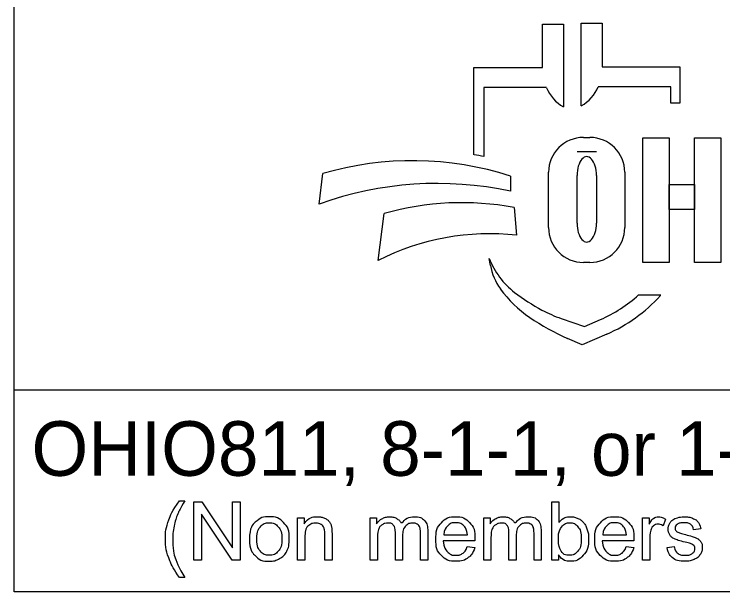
# Model space of a CAD drawing. Extents: x 0 to 34, y 0 to 22.
# Drawn here: x 2.378 to 4.196, y 2.143 to 3.625 of the extents above; entities that cross this region are included whole.
import ezdxf

# ---------------------------------------------------------------- set-up
doc = ezdxf.new("R2010")
doc.units = 0
doc.layers.add('SH_Data', color=7, linetype='Continuous')
doc.layers.add('SH_Text', color=7, linetype='Continuous')

msp = doc.modelspace()

# ---------------------------------------------------------------- linework, layer by layer
at = {"layer": 'SH_Data'}
for p, q in [((2.3775, 2.1428), (2.3775, 4.4803)), ((2.3775, 2.1428), (2.3775, 4.4803)), ((6.6275, 2.6607), (2.3775, 2.6607)), ((6.6275, 2.6607), (2.3775, 2.6607)), ((6.6275, 2.1428), (2.3775, 2.1428)), ((6.6275, 2.1428), (2.3775, 2.1428))]:
    msp.add_line(p, q, dxfattribs=at)
at = {"layer": 'SH_Text'}
for p, q in [((3.8329, 3.39), (3.8329, 3.6021)), ((3.8329, 3.6021), (3.8865, 3.6021)), ((3.8329, 3.39), (3.8329, 3.6021)), ((3.8329, 3.6021), (3.8865, 3.6021)), ((3.8865, 3.6021), (3.8865, 3.4906)), ((3.8865, 3.6021), (3.8865, 3.4906)), ((3.7335, 3.4883), (3.7335, 3.5998)), ((3.7335, 3.5998), (3.7872, 3.5998)), ((3.7335, 3.4883), (3.7335, 3.5998)), ((3.7335, 3.5998), (3.7872, 3.5998)), ((3.7872, 3.5998), (3.7872, 3.3877)), ((3.7872, 3.5998), (3.7872, 3.3877)), ((3.5576, 3.2644), (3.5576, 3.4883)), ((3.5576, 3.4883), (3.7335, 3.4883)), ((3.5576, 3.2644), (3.5576, 3.4883)), ((3.5576, 3.4883), (3.7335, 3.4883)), ((3.8865, 3.4906), (4.0857, 3.4906)), ((3.8865, 3.4906), (4.0857, 3.4906)), ((4.0857, 3.4906), (4.0857, 3.3968)), ((4.0857, 3.4906), (4.0857, 3.3968)), ((4.0625, 3.4392), (3.8761, 3.4392)), ((4.0625, 3.4392), (3.8761, 3.4392)), ((4.0625, 3.3968), (4.0625, 3.4392)), ((4.0625, 3.3968), (4.0625, 3.4392)), ((3.5828, 3.4369), (3.5828, 3.26)), ((3.7439, 3.4369), (3.5828, 3.4369)), ((3.5828, 3.4369), (3.5828, 3.26)), ((3.7439, 3.4369), (3.5828, 3.4369)), ((4.0857, 3.3968), (4.0625, 3.3968)), ((4.0857, 3.3968), (4.0625, 3.3968)), ((3.8385, 3.3091), (3.8551, 3.3091)), ((3.8385, 3.3091), (3.8551, 3.3091)), ((3.8718, 3.2721), (3.822, 3.2721)), ((3.8718, 3.2721), (3.822, 3.2721)), ((3.7491, 3.0776), (3.7491, 3.2196)), ((3.7491, 3.0776), (3.7491, 3.2196)), ((3.9445, 3.2196), (3.9445, 3.0776)), ((3.9445, 3.2196), (3.9445, 3.0776)), ((3.1602, 3.1381), (3.1696, 3.2162)), ((3.1602, 3.1381), (3.1696, 3.2162)), ((3.6509, 3.2097), (3.6509, 3.1709)), ((3.6509, 3.2097), (3.6509, 3.1709)), ((3.822, 3.089), (3.822, 3.2114)), ((3.822, 3.089), (3.822, 3.2114)), ((3.8718, 3.2114), (3.8718, 3.089)), ((3.8718, 3.2114), (3.8718, 3.089)), ((3.6608, 3.1291), (3.6671, 3.0582)), ((3.6608, 3.1291), (3.6671, 3.0582)), ((3.312, 2.9936), (3.3267, 3.1137)), ((3.312, 2.9936), (3.3267, 3.1137)), ((3.5997, 2.9807), (3.5967, 2.9986)), ((3.5997, 2.9807), (3.5967, 2.9986)), ((3.8551, 2.9882), (3.8385, 2.9882)), ((3.8551, 2.9882), (3.8385, 2.9882)), ((3.98, 2.9048), (4.0375, 2.9048)), ((3.98, 2.9048), (4.0375, 2.9048)), ((3.7816, 2.8444), (3.841, 2.8239)), ((3.7816, 2.8444), (3.841, 2.8239)), ((3.841, 2.8239), (3.8821, 2.8417)), ((3.841, 2.8239), (3.8821, 2.8417)), ((3.8983, 2.8044), (3.835, 2.7769)), ((3.8983, 2.8044), (3.835, 2.7769)), ((3.835, 2.7769), (3.7976, 2.7934)), ((3.835, 2.7769), (3.7976, 2.7934))]:
    msp.add_line(p, q, dxfattribs=at)
for points in [[(3.991, 3.3081), (4.0589, 3.3081), (4.0589, 2.9881), (3.991, 2.9881)], [(3.991, 3.3081), (4.0589, 3.3081), (4.0589, 2.9881), (3.991, 2.9881)], [(4.1231, 3.3081), (4.1911, 3.3081), (4.1911, 2.9881), (4.1231, 2.9881)], [(4.1231, 3.3081), (4.1911, 3.3081), (4.1911, 2.9881), (4.1231, 2.9881)], [(4.0589, 3.1882), (4.1231, 3.1882), (4.1231, 3.1242), (4.0589, 3.1242)], [(4.0589, 3.1882), (4.1231, 3.1882), (4.1231, 3.1242), (4.0589, 3.1242)]]:
    msp.add_lwpolyline(points, close=True, dxfattribs=at)
for points in [[(2.8021, 2.3766), (2.8153, 2.3766)], [(2.8021, 2.3766), (2.8153, 2.3766)], [(2.8389, 2.2239), (2.8389, 2.3741), (2.8592, 2.3741), (2.9382, 2.2561), (2.9382, 2.3741), (2.9572, 2.3741), (2.9572, 2.2239), (2.9369, 2.2239), (2.8579, 2.3419), (2.8579, 2.2239), (2.8389, 2.2239)], [(2.8389, 2.2239), (2.8389, 2.3741), (2.8592, 2.3741), (2.9382, 2.2561), (2.9382, 2.3741), (2.9572, 2.3741), (2.9572, 2.2239), (2.9369, 2.2239), (2.8579, 2.3419), (2.8579, 2.2239), (2.8389, 2.2239)], [(3.7743, 2.2239), (3.7573, 2.2239), (3.7573, 2.3741), (3.7757, 2.3741), (3.7757, 2.3206)], [(3.7743, 2.2239), (3.7573, 2.2239), (3.7573, 2.3741), (3.7757, 2.3741), (3.7757, 2.3206)], [(3.1048, 2.2239), (3.1048, 2.3328), (3.1214, 2.3328), (3.1214, 2.3173)], [(3.1048, 2.2239), (3.1048, 2.3328), (3.1214, 2.3328), (3.1214, 2.3173)], [(3.2912, 2.2239), (3.2912, 2.3328), (3.3077, 2.3328), (3.3077, 2.3174)], [(3.2912, 2.2239), (3.2912, 2.3328), (3.3077, 2.3328), (3.3077, 2.3174)], [(3.5826, 2.2239), (3.5826, 2.3328), (3.5991, 2.3328), (3.5991, 2.3174)], [(3.5826, 2.2239), (3.5826, 2.3328), (3.5991, 2.3328), (3.5991, 2.3174)], [(3.9904, 2.2239), (3.9904, 2.3328), (4.007, 2.3328), (4.007, 2.3163)], [(3.9904, 2.2239), (3.9904, 2.3328), (4.007, 2.3328), (4.007, 2.3163)], [(4.0495, 2.3293), (4.043, 2.3122)], [(4.0495, 2.3293), (4.043, 2.3122)], [(3.3743, 2.2871), (3.3743, 2.2239), (3.3559, 2.2239), (3.3559, 2.2946)], [(3.3743, 2.2871), (3.3743, 2.2239), (3.3559, 2.2239), (3.3559, 2.2946)], [(3.4388, 2.2986), (3.4388, 2.2239), (3.4203, 2.2239), (3.4203, 2.2924)], [(3.4388, 2.2986), (3.4388, 2.2239), (3.4203, 2.2239), (3.4203, 2.2924)], [(3.6657, 2.2871), (3.6657, 2.2239), (3.6473, 2.2239), (3.6473, 2.2946)], [(3.6657, 2.2871), (3.6657, 2.2239), (3.6473, 2.2239), (3.6473, 2.2946)], [(3.7301, 2.2986), (3.7301, 2.2239), (3.7117, 2.2239), (3.7117, 2.2924)], [(3.7301, 2.2986), (3.7301, 2.2239), (3.7117, 2.2239), (3.7117, 2.2924)], [(4.1394, 2.3046), (4.1213, 2.3022)], [(4.1394, 2.3046), (4.1213, 2.3022)], [(3.1233, 2.2833), (3.1233, 2.2239), (3.1048, 2.2239)], [(3.1233, 2.2833), (3.1233, 2.2239), (3.1048, 2.2239)], [(3.1932, 2.2908), (3.1932, 2.2239), (3.1748, 2.2239), (3.1748, 2.2901)], [(3.1932, 2.2908), (3.1932, 2.2239), (3.1748, 2.2239), (3.1748, 2.2901)], [(3.3097, 2.2803), (3.3097, 2.2239), (3.2912, 2.2239)], [(3.3097, 2.2803), (3.3097, 2.2239), (3.2912, 2.2239)], [(3.56, 2.2736), (3.4788, 2.2736)], [(3.56, 2.2736), (3.4788, 2.2736)], [(3.4799, 2.2887), (3.5406, 2.2887)], [(3.4799, 2.2887), (3.5406, 2.2887)], [(3.601, 2.2803), (3.601, 2.2239), (3.5826, 2.2239)], [(3.601, 2.2803), (3.601, 2.2239), (3.5826, 2.2239)], [(3.968, 2.2736), (3.8868, 2.2736)], [(3.968, 2.2736), (3.8868, 2.2736)], [(3.8879, 2.2887), (3.9486, 2.2887)], [(3.8879, 2.2887), (3.9486, 2.2887)], [(4.0088, 2.2809), (4.0088, 2.2239), (3.9904, 2.2239)], [(4.0088, 2.2809), (4.0088, 2.2239), (3.9904, 2.2239)], [(3.5404, 2.2591), (3.5595, 2.2567)], [(3.5404, 2.2591), (3.5595, 2.2567)], [(3.9484, 2.2591), (3.9675, 2.2567)], [(3.9484, 2.2591), (3.9675, 2.2567)], [(4.053, 2.2564), (4.0712, 2.2593)], [(4.053, 2.2564), (4.0712, 2.2593)], [(3.7743, 2.2375), (3.7743, 2.2239)], [(3.7743, 2.2375), (3.7743, 2.2239)], [(2.8153, 2.1798), (2.8021, 2.1798)], [(2.8153, 2.1798), (2.8021, 2.1798)]]:
    msp.add_lwpolyline(points, dxfattribs=at)
for centre, radius, start, end in [((3.7847, 3.476), 0.0985, 299.2531, 338.0704), ((3.7847, 3.476), 0.0985, 299.2531, 338.0704), ((3.8353, 3.4736), 0.0985, 201.9296, 240.7469), ((3.8353, 3.4736), 0.0985, 201.9296, 240.7469), ((3.8385, 3.2196), 0.0895, 90, 180), ((3.8385, 3.2196), 0.0895, 90, 180), ((3.8551, 3.2196), 0.0895, 0, 90), ((3.8551, 3.2196), 0.0895, 0, 90), ((3.4295, 2.4554), 0.8191, 79.2074, 81.0007), ((3.4295, 2.4554), 0.8191, 79.2074, 81.0007), ((3.3997, 2.4302), 0.8191, 72.1402, 106.3144), ((3.3997, 2.4302), 0.8191, 72.1402, 106.3144), ((3.4628, 2.2991), 0.8919, 77.8238, 109.8274), ((3.4628, 2.2991), 0.8919, 77.8238, 109.8274), ((3.5267, 2.4094), 0.7322, 79.44, 105.8467), ((3.5267, 2.4094), 0.7322, 79.44, 105.8467), ((3.8385, 3.0776), 0.0895, 180, 270), ((3.8385, 3.0776), 0.0895, 180, 270), ((3.8551, 3.0776), 0.0895, 270, 0), ((3.8551, 3.0776), 0.0895, 270, 0), ((3.5987, 2.4262), 0.6357, 83.8248, 116.8021), ((3.5987, 2.4262), 0.6357, 83.8248, 116.8021), ((3.7841, 3.0707), 0.2008, 201.0457, 232.5314), ((3.7841, 3.0707), 0.2008, 201.0457, 232.5314), ((3.741, 3.0048), 0.1433, 189.6817, 216.0884), ((3.741, 3.0048), 0.1433, 189.6817, 216.0884), ((3.8747, 3.1022), 0.3088, 216.0884, 235.7167), ((3.8747, 3.1022), 0.3088, 216.0884, 235.7167), ((3.9766, 3.3219), 0.5173, 232.5314, 241.794), ((3.9766, 3.3219), 0.5173, 232.5314, 241.794), ((3.7387, 3.1722), 0.3602, 293.4582, 312.0712), ((3.7387, 3.1722), 0.3602, 293.4582, 312.0712), ((3.7387, 3.1722), 0.401, 293.4582, 317.8286), ((3.7387, 3.1722), 0.401, 293.4582, 317.8286), ((3.8914, 3.1631), 0.3371, 241.794, 250.9821), ((3.8914, 3.1631), 0.3371, 241.794, 250.9821), ((4.0412, 3.3465), 0.6044, 235.7167, 246.2325), ((4.0412, 3.3465), 0.6044, 235.7167, 246.2325)]:
    msp.add_arc(centre, radius, start, end, dxfattribs=at)
for centre, start_param, end_param in [((3.8469, 3.2114), 4.712389, 7.853982), ((3.8469, 3.2114), 4.712389, 7.853982), ((3.8469, 3.089), 1.570796, 4.712389), ((3.8469, 3.089), 1.570796, 4.712389)]:
    msp.add_ellipse(centre, major_axis=(0, 0.0484), ratio=0.514403, start_param=start_param, end_param=end_param, dxfattribs=at)
for points in [[(2.8021, 2.1798), (2.7869, 2.199), (2.7763, 2.2248), (2.7657, 2.2506), (2.7657, 2.2783), (2.7657, 2.3026), (2.7736, 2.325), (2.7829, 2.3509), (2.8021, 2.3766)], [(2.8021, 2.1798), (2.7869, 2.199), (2.7763, 2.2248), (2.7657, 2.2506), (2.7657, 2.2783), (2.7657, 2.3026), (2.7736, 2.325), (2.7829, 2.3509), (2.8021, 2.3766)], [(2.8153, 2.3766), (2.8029, 2.3553), (2.7989, 2.3462), (2.7927, 2.332), (2.7891, 2.3167), (2.7847, 2.2975), (2.7847, 2.2782), (2.7847, 2.2289), (2.8153, 2.1798)], [(2.8153, 2.3766), (2.8029, 2.3553), (2.7989, 2.3462), (2.7927, 2.332), (2.7891, 2.3167), (2.7847, 2.2975), (2.7847, 2.2782), (2.7847, 2.2289), (2.8153, 2.1798)], [(2.9814, 2.2783), (2.9814, 2.3085), (2.9981, 2.3231), (3.0122, 2.3352), (3.0323, 2.3352), (3.0547, 2.3352), (3.069, 2.3205), (3.0832, 2.3058), (3.0832, 2.2799), (3.0832, 2.2589), (3.0769, 2.2469), (3.0706, 2.2348), (3.0586, 2.2282), (3.0466, 2.2215), (3.0323, 2.2215), (3.0095, 2.2215), (2.9954, 2.2362), (2.9814, 2.2508), (2.9814, 2.2783)], [(2.9814, 2.2783), (2.9814, 2.3085), (2.9981, 2.3231), (3.0122, 2.3352), (3.0323, 2.3352), (3.0547, 2.3352), (3.069, 2.3205), (3.0832, 2.3058), (3.0832, 2.2799), (3.0832, 2.2589), (3.0769, 2.2469), (3.0706, 2.2348), (3.0586, 2.2282), (3.0466, 2.2215), (3.0323, 2.2215), (3.0095, 2.2215), (2.9954, 2.2362), (2.9814, 2.2508), (2.9814, 2.2783)], [(3.1214, 2.3173), (3.1334, 2.3352), (3.156, 2.3352), (3.1659, 2.3352), (3.1741, 2.3316), (3.1823, 2.3281), (3.1864, 2.3224), (3.1905, 2.3166), (3.1922, 2.3087), (3.1932, 2.3036), (3.1932, 2.2908)], [(3.1214, 2.3173), (3.1334, 2.3352), (3.156, 2.3352), (3.1659, 2.3352), (3.1741, 2.3316), (3.1823, 2.3281), (3.1864, 2.3224), (3.1905, 2.3166), (3.1922, 2.3087), (3.1932, 2.3036), (3.1932, 2.2908)], [(3.3077, 2.3174), (3.3128, 2.3254), (3.3214, 2.3303), (3.3299, 2.3352), (3.3407, 2.3352), (3.3528, 2.3352), (3.3606, 2.3301), (3.3683, 2.3251), (3.3715, 2.3161), (3.3844, 2.3352), (3.4051, 2.3352), (3.4213, 2.3352), (3.43, 2.3262), (3.4388, 2.3172), (3.4388, 2.2986)], [(3.3077, 2.3174), (3.3128, 2.3254), (3.3214, 2.3303), (3.3299, 2.3352), (3.3407, 2.3352), (3.3528, 2.3352), (3.3606, 2.3301), (3.3683, 2.3251), (3.3715, 2.3161), (3.3844, 2.3352), (3.4051, 2.3352), (3.4213, 2.3352), (3.43, 2.3262), (3.4388, 2.3172), (3.4388, 2.2986)], [(3.5595, 2.2567), (3.555, 2.24), (3.5428, 2.2307), (3.5306, 2.2215), (3.5117, 2.2215), (3.4878, 2.2215), (3.4738, 2.2362), (3.4598, 2.2509), (3.4598, 2.2774), (3.4598, 2.3049), (3.474, 2.32), (3.4881, 2.3352), (3.5106, 2.3352), (3.5324, 2.3352), (3.5463, 2.3203), (3.5601, 2.3055), (3.5601, 2.2785), (3.5601, 2.2769), (3.56, 2.2736)], [(3.5595, 2.2567), (3.555, 2.24), (3.5428, 2.2307), (3.5306, 2.2215), (3.5117, 2.2215), (3.4878, 2.2215), (3.4738, 2.2362), (3.4598, 2.2509), (3.4598, 2.2774), (3.4598, 2.3049), (3.474, 2.32), (3.4881, 2.3352), (3.5106, 2.3352), (3.5324, 2.3352), (3.5463, 2.3203), (3.5601, 2.3055), (3.5601, 2.2785), (3.5601, 2.2769), (3.56, 2.2736)], [(3.5991, 2.3174), (3.6042, 2.3254), (3.6127, 2.3303), (3.6212, 2.3352), (3.6321, 2.3352), (3.6442, 2.3352), (3.6519, 2.3301), (3.6597, 2.3251), (3.6628, 2.3161), (3.6758, 2.3352), (3.6965, 2.3352), (3.7127, 2.3352), (3.7214, 2.3262), (3.7301, 2.3172), (3.7301, 2.2986)], [(3.5991, 2.3174), (3.6042, 2.3254), (3.6127, 2.3303), (3.6212, 2.3352), (3.6321, 2.3352), (3.6442, 2.3352), (3.6519, 2.3301), (3.6597, 2.3251), (3.6628, 2.3161), (3.6758, 2.3352), (3.6965, 2.3352), (3.7127, 2.3352), (3.7214, 2.3262), (3.7301, 2.3172), (3.7301, 2.2986)], [(3.7757, 2.3206), (3.7874, 2.3352), (3.8055, 2.3352), (3.8155, 2.3352), (3.8245, 2.3311), (3.8335, 2.3271), (3.8392, 2.3198), (3.845, 2.3124), (3.8483, 2.3021), (3.8516, 2.2918), (3.8516, 2.28), (3.8516, 2.252), (3.8378, 2.2368), (3.8239, 2.2215), (3.8046, 2.2215), (3.7853, 2.2215), (3.7743, 2.2375)], [(3.7757, 2.3206), (3.7874, 2.3352), (3.8055, 2.3352), (3.8155, 2.3352), (3.8245, 2.3311), (3.8335, 2.3271), (3.8392, 2.3198), (3.845, 2.3124), (3.8483, 2.3021), (3.8516, 2.2918), (3.8516, 2.28), (3.8516, 2.252), (3.8378, 2.2368), (3.8239, 2.2215), (3.8046, 2.2215), (3.7853, 2.2215), (3.7743, 2.2375)], [(3.9675, 2.2567), (3.963, 2.24), (3.9508, 2.2307), (3.9386, 2.2215), (3.9196, 2.2215), (3.8958, 2.2215), (3.8818, 2.2362), (3.8678, 2.2509), (3.8678, 2.2774), (3.8678, 2.3049), (3.882, 2.32), (3.8961, 2.3352), (3.9186, 2.3352), (3.9404, 2.3352), (3.9543, 2.3203), (3.9681, 2.3055), (3.9681, 2.2785), (3.9681, 2.2769), (3.968, 2.2736)], [(3.9675, 2.2567), (3.963, 2.24), (3.9508, 2.2307), (3.9386, 2.2215), (3.9196, 2.2215), (3.8958, 2.2215), (3.8818, 2.2362), (3.8678, 2.2509), (3.8678, 2.2774), (3.8678, 2.3049), (3.882, 2.32), (3.8961, 2.3352), (3.9186, 2.3352), (3.9404, 2.3352), (3.9543, 2.3203), (3.9681, 2.3055), (3.9681, 2.2785), (3.9681, 2.2769), (3.968, 2.2736)], [(4.007, 2.3163), (4.0133, 2.3278), (4.0187, 2.3315), (4.0241, 2.3352), (4.0305, 2.3352), (4.0398, 2.3352), (4.0495, 2.3293)], [(4.007, 2.3163), (4.0133, 2.3278), (4.0187, 2.3315), (4.0241, 2.3352), (4.0305, 2.3352), (4.0398, 2.3352), (4.0495, 2.3293)], [(4.0712, 2.2593), (4.0727, 2.2483), (4.0798, 2.2425), (4.0868, 2.2366), (4.0995, 2.2366), (4.1122, 2.2366), (4.1184, 2.2418), (4.1245, 2.247), (4.1245, 2.254), (4.1245, 2.2602), (4.1191, 2.2638), (4.1153, 2.2663), (4.1002, 2.2701), (4.0799, 2.2752), (4.072, 2.2789), (4.0642, 2.2827), (4.0601, 2.2893), (4.0561, 2.2959), (4.0561, 2.3038), (4.0561, 2.3111), (4.0594, 2.3173), (4.0628, 2.3235), (4.0685, 2.3276), (4.0728, 2.3308), (4.0803, 2.333), (4.0877, 2.3352), (4.0962, 2.3352), (4.109, 2.3352), (4.1187, 2.3315), (4.1284, 2.3278), (4.133, 2.3215), (4.1377, 2.3152), (4.1394, 2.3046)], [(4.0712, 2.2593), (4.0727, 2.2483), (4.0798, 2.2425), (4.0868, 2.2366), (4.0995, 2.2366), (4.1122, 2.2366), (4.1184, 2.2418), (4.1245, 2.247), (4.1245, 2.254), (4.1245, 2.2602), (4.1191, 2.2638), (4.1153, 2.2663), (4.1002, 2.2701), (4.0799, 2.2752), (4.072, 2.2789), (4.0642, 2.2827), (4.0601, 2.2893), (4.0561, 2.2959), (4.0561, 2.3038), (4.0561, 2.3111), (4.0594, 2.3173), (4.0628, 2.3235), (4.0685, 2.3276), (4.0728, 2.3308), (4.0803, 2.333), (4.0877, 2.3352), (4.0962, 2.3352), (4.109, 2.3352), (4.1187, 2.3315), (4.1284, 2.3278), (4.133, 2.3215), (4.1377, 2.3152), (4.1394, 2.3046)], [(3.0003, 2.2783), (3.0003, 2.2574), (3.0094, 2.247), (3.0185, 2.2366), (3.0323, 2.2366), (3.046, 2.2366), (3.0551, 2.2471), (3.0642, 2.2575), (3.0642, 2.279), (3.0642, 2.2991), (3.0551, 2.3095), (3.0459, 2.3199), (3.0323, 2.3199), (3.0185, 2.3199), (3.0094, 2.3096), (3.0003, 2.2992), (3.0003, 2.2783)], [(3.0003, 2.2783), (3.0003, 2.2574), (3.0094, 2.247), (3.0185, 2.2366), (3.0323, 2.2366), (3.046, 2.2366), (3.0551, 2.2471), (3.0642, 2.2575), (3.0642, 2.279), (3.0642, 2.2991), (3.0551, 2.3095), (3.0459, 2.3199), (3.0323, 2.3199), (3.0185, 2.3199), (3.0094, 2.3096), (3.0003, 2.2992), (3.0003, 2.2783)], [(3.1748, 2.2901), (3.1748, 2.3013), (3.1726, 2.3069), (3.1705, 2.3125), (3.165, 2.3158), (3.1595, 2.3191), (3.1521, 2.3191), (3.1404, 2.3191), (3.1318, 2.3117), (3.1233, 2.3042), (3.1233, 2.2833)], [(3.1748, 2.2901), (3.1748, 2.3013), (3.1726, 2.3069), (3.1705, 2.3125), (3.165, 2.3158), (3.1595, 2.3191), (3.1521, 2.3191), (3.1404, 2.3191), (3.1318, 2.3117), (3.1233, 2.3042), (3.1233, 2.2833)], [(3.3559, 2.2946), (3.3559, 2.3069), (3.3514, 2.313), (3.3469, 2.3191), (3.3366, 2.3191), (3.3288, 2.3191), (3.3222, 2.315), (3.3156, 2.311), (3.3126, 2.3031), (3.3097, 2.2952), (3.3097, 2.2803)], [(3.3559, 2.2946), (3.3559, 2.3069), (3.3514, 2.313), (3.3469, 2.3191), (3.3366, 2.3191), (3.3288, 2.3191), (3.3222, 2.315), (3.3156, 2.311), (3.3126, 2.3031), (3.3097, 2.2952), (3.3097, 2.2803)], [(3.4203, 2.2924), (3.4203, 2.3035), (3.4185, 2.3083), (3.4168, 2.3132), (3.412, 2.3162), (3.4073, 2.3191), (3.401, 2.3191), (3.3895, 2.3191), (3.3819, 2.3115), (3.3743, 2.3039), (3.3743, 2.2871)], [(3.4203, 2.2924), (3.4203, 2.3035), (3.4185, 2.3083), (3.4168, 2.3132), (3.412, 2.3162), (3.4073, 2.3191), (3.401, 2.3191), (3.3895, 2.3191), (3.3819, 2.3115), (3.3743, 2.3039), (3.3743, 2.2871)], [(3.5406, 2.2887), (3.5394, 2.3025), (3.5337, 2.3094), (3.5249, 2.3201), (3.5108, 2.3201), (3.4981, 2.3201), (3.4894, 2.3115), (3.4808, 2.303), (3.4799, 2.2887)], [(3.5406, 2.2887), (3.5394, 2.3025), (3.5337, 2.3094), (3.5249, 2.3201), (3.5108, 2.3201), (3.4981, 2.3201), (3.4894, 2.3115), (3.4808, 2.303), (3.4799, 2.2887)], [(3.6473, 2.2946), (3.6473, 2.3069), (3.6428, 2.313), (3.6383, 2.3191), (3.628, 2.3191), (3.6202, 2.3191), (3.6136, 2.315), (3.607, 2.311), (3.604, 2.3031), (3.601, 2.2952), (3.601, 2.2803)], [(3.6473, 2.2946), (3.6473, 2.3069), (3.6428, 2.313), (3.6383, 2.3191), (3.628, 2.3191), (3.6202, 2.3191), (3.6136, 2.315), (3.607, 2.311), (3.604, 2.3031), (3.601, 2.2952), (3.601, 2.2803)], [(3.7117, 2.2924), (3.7117, 2.3035), (3.7099, 2.3083), (3.7081, 2.3132), (3.7034, 2.3162), (3.6987, 2.3191), (3.6923, 2.3191), (3.6809, 2.3191), (3.6733, 2.3115), (3.6657, 2.3039), (3.6657, 2.2871)], [(3.7117, 2.2924), (3.7117, 2.3035), (3.7099, 2.3083), (3.7081, 2.3132), (3.7034, 2.3162), (3.6987, 2.3191), (3.6923, 2.3191), (3.6809, 2.3191), (3.6733, 2.3115), (3.6657, 2.3039), (3.6657, 2.2871)], [(3.7741, 2.2792), (3.7741, 2.2596), (3.7794, 2.2509), (3.7881, 2.2366), (3.8029, 2.2366), (3.815, 2.2366), (3.8238, 2.2471), (3.8326, 2.2576), (3.8326, 2.2784), (3.8326, 2.2998), (3.8241, 2.3099), (3.8157, 2.3201), (3.8038, 2.3201), (3.7917, 2.3201), (3.7829, 2.3096), (3.7741, 2.299), (3.7741, 2.2792)], [(3.7741, 2.2792), (3.7741, 2.2596), (3.7794, 2.2509), (3.7881, 2.2366), (3.8029, 2.2366), (3.815, 2.2366), (3.8238, 2.2471), (3.8326, 2.2576), (3.8326, 2.2784), (3.8326, 2.2998), (3.8241, 2.3099), (3.8157, 2.3201), (3.8038, 2.3201), (3.7917, 2.3201), (3.7829, 2.3096), (3.7741, 2.299), (3.7741, 2.2792)], [(3.9486, 2.2887), (3.9474, 2.3025), (3.9417, 2.3094), (3.9328, 2.3201), (3.9188, 2.3201), (3.9061, 2.3201), (3.8974, 2.3115), (3.8888, 2.303), (3.8879, 2.2887)], [(3.9486, 2.2887), (3.9474, 2.3025), (3.9417, 2.3094), (3.9328, 2.3201), (3.9188, 2.3201), (3.9061, 2.3201), (3.8974, 2.3115), (3.8888, 2.303), (3.8879, 2.2887)], [(4.043, 2.3122), (4.0363, 2.3162), (4.0295, 2.3162), (4.0235, 2.3162), (4.0187, 2.3125), (4.0139, 2.3089), (4.0119, 2.3024), (4.0088, 2.2926), (4.0088, 2.2809)], [(4.043, 2.3122), (4.0363, 2.3162), (4.0295, 2.3162), (4.0235, 2.3162), (4.0187, 2.3125), (4.0139, 2.3089), (4.0119, 2.3024), (4.0088, 2.2926), (4.0088, 2.2809)], [(4.1213, 2.3022), (4.1201, 2.3106), (4.1142, 2.3153), (4.1083, 2.3201), (4.0975, 2.3201), (4.0848, 2.3201), (4.0794, 2.3159), (4.0739, 2.3116), (4.0739, 2.306), (4.0739, 2.3024), (4.0762, 2.2995), (4.0785, 2.2966), (4.0833, 2.2946), (4.086, 2.2936), (4.0996, 2.2899), (4.1192, 2.2847), (4.1269, 2.2813), (4.1347, 2.278), (4.1391, 2.2717), (4.1435, 2.2653), (4.1435, 2.2559), (4.1435, 2.2467), (4.1381, 2.2386), (4.1327, 2.2304), (4.1226, 2.226), (4.1124, 2.2215), (4.0996, 2.2215), (4.0784, 2.2215), (4.0672, 2.2303), (4.0561, 2.2391), (4.053, 2.2564)], [(4.1213, 2.3022), (4.1201, 2.3106), (4.1142, 2.3153), (4.1083, 2.3201), (4.0975, 2.3201), (4.0848, 2.3201), (4.0794, 2.3159), (4.0739, 2.3116), (4.0739, 2.306), (4.0739, 2.3024), (4.0762, 2.2995), (4.0785, 2.2966), (4.0833, 2.2946), (4.086, 2.2936), (4.0996, 2.2899), (4.1192, 2.2847), (4.1269, 2.2813), (4.1347, 2.278), (4.1391, 2.2717), (4.1435, 2.2653), (4.1435, 2.2559), (4.1435, 2.2467), (4.1381, 2.2386), (4.1327, 2.2304), (4.1226, 2.226), (4.1124, 2.2215), (4.0996, 2.2215), (4.0784, 2.2215), (4.0672, 2.2303), (4.0561, 2.2391), (4.053, 2.2564)], [(3.4788, 2.2736), (3.4799, 2.2557), (3.489, 2.2462), (3.4981, 2.2366), (3.5117, 2.2366), (3.5219, 2.2366), (3.5291, 2.242), (3.5362, 2.2473), (3.5404, 2.2591)], [(3.4788, 2.2736), (3.4799, 2.2557), (3.489, 2.2462), (3.4981, 2.2366), (3.5117, 2.2366), (3.5219, 2.2366), (3.5291, 2.242), (3.5362, 2.2473), (3.5404, 2.2591)], [(3.8868, 2.2736), (3.8879, 2.2557), (3.897, 2.2462), (3.9061, 2.2366), (3.9197, 2.2366), (3.9299, 2.2366), (3.937, 2.242), (3.9442, 2.2473), (3.9484, 2.2591)], [(3.8868, 2.2736), (3.8879, 2.2557), (3.897, 2.2462), (3.9061, 2.2366), (3.9197, 2.2366), (3.9299, 2.2366), (3.937, 2.242), (3.9442, 2.2473), (3.9484, 2.2591)]]:
    msp.add_open_spline(points, degree=3, dxfattribs=at)

# ---------------------------------------------------------------- texts
msp.add_text('OHIO811, 8-1-1, or 1-800-362-2764', height=0.14, dxfattribs=at).set_placement((2.422, 2.4406))
msp.add_text('OHIO811, 8-1-1, or 1-800-362-2764', height=0.14, dxfattribs=at).set_placement((2.422, 2.4406))

doc.saveas('drawing.dxf')
